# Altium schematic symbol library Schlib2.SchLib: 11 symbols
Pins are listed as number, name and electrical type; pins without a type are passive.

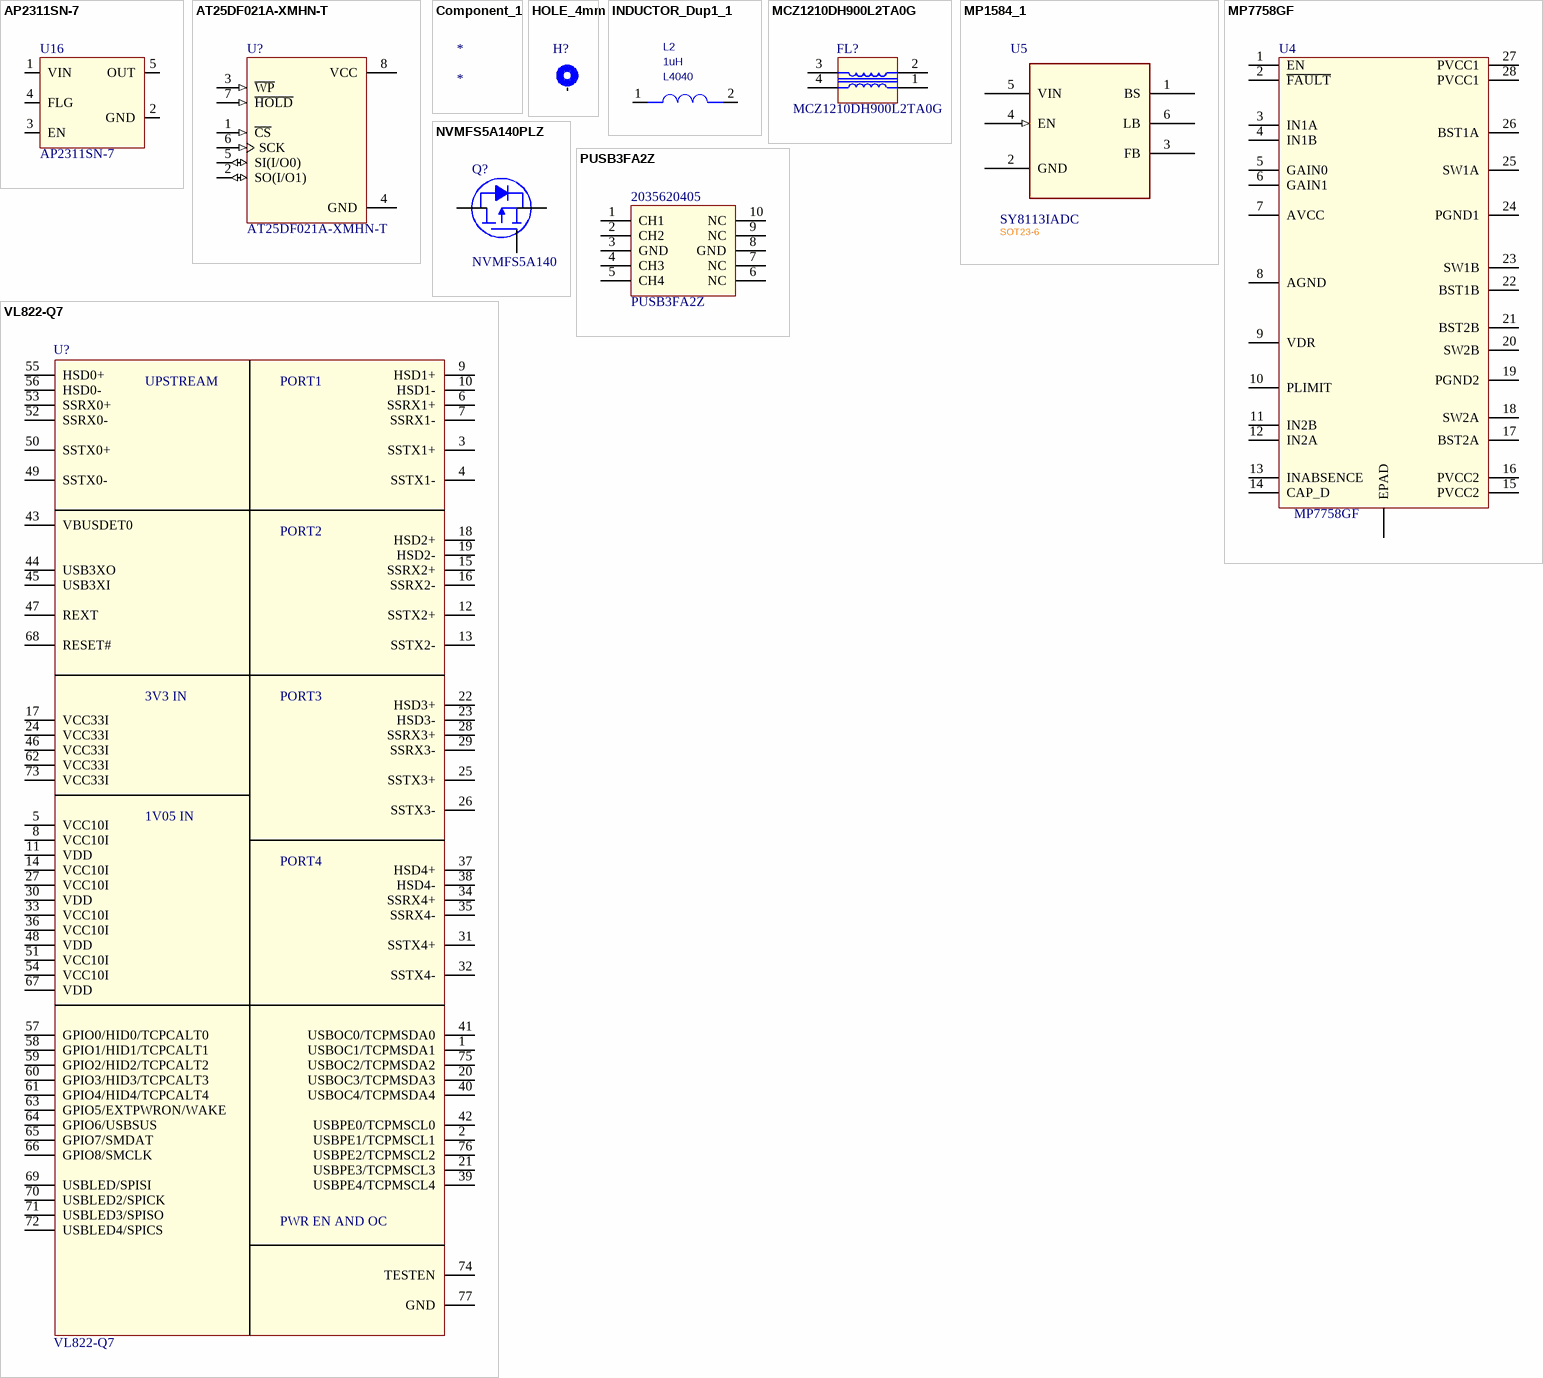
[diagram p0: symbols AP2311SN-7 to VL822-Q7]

## AP2311SN-7
designator U16
Power Switch ICs - Power Distribution 2.0A SGL CH 70mOhm 2.5A 2.7 to 5.5V
footprint AP2301SN-7 (Power Switch ICs - Power Distribution 2.0A SGL CH 70mOhm 2.5A 2.7 to 5.5V)
pins: 1 VIN, 2 GND, 3 EN, 4 FLG, 5 OUT

## AT25DF021A-XMHN-T
designator U?
IC FLASH 2MBIT SPI 104MHZ 8TSSOP
footprint AT25DF512C-XMHNGU-B (NOR Flash 512Kb, 1.65V, 85Mhz Serial Flash)
pins: 1 ~{CS} (in), 2 SO(I/O1) (io), 3 ~{WP} (in), 4 GND (power), 5 SI(I/O0) (io), 6 SCK (in), 7 ~{HOLD} (in), 8 VCC (power)

## Component_1
designator *

## HOLE_4mm
designator H?, comment HOLE_4.1mm  (value not drawn)
PART_NUMBER: PCB²âÊÔµã; Manufacturer: NA; Remarks: pcb; PCB Footprint: M2.0_3.6
footprint M2.0_3.6
pins: 1

## INDUCTOR_Dup1_1
designator L2, comment 1uH  PCB Footprint: L4040
PART_NUMBER: FDSD0420D-1R0M
footprint L4040
pins: 1, 2

## MCZ1210DH900L2TA0G
designator FL?
Common Mode Chokes / Filters 0504 90ohms 2 Lines HDMI, DVI, USB3.0; Manufacturer_Name: TDK; Manufacturer_Part_Number: MCZ1210DH500L2TA0G
footprint MCZ1210DH
pins: 1, 2, 3, 4

## MP1584_1
designator U5, comment SY8113IADC  PCB Footprint: SOT23-6
footprint SOT23-6
pins: 1 BS, 2 GND (power), 3 FB, 4 EN (in), 5 VIN (power), 6 LB

## MP7758GF
designator U4
Amplifier IC 2-Channel (Stereo) Class D 28-TSSOP-EP; Manufacturer: Monolithic Power Systems Inc.; Part Number: MP7758GF-Z
footprint MP7758GF (TSSOP-28)
pins: 1 EN, 2 ~{FAULT}, 3 IN1A, 4 IN1B, 5 GAIN0, 6 GAIN1, 7 AVCC, 8 AGND, 9 VDR, 10 PLIMIT, 11 IN2B, 12 IN2A, 13 INABSENCE, 14 CAP_D, 15 PVCC2, 16 PVCC2, 17 BST2A, 18 SW2A, 19 PGND2, 20 SW2B, 21 BST2B, 22 BST1B, 23 SW1B, 24 PGND1, 25 SW1A, 26 BST1A, 27 PVCC1, 28 PVCC1, EPAD

## NVMFS5A140PLZ
designator Q?, comment NVMFS5A140
Single P-Channel Power MOSFET, -40 V, -140 A; Part Number: BSZ067N06LS3GATMA1; Manufacturer: Infineon Technologies; Current - Continuous Drain (Id) @ 25°C: 14A (Ta), 20A (Tc); Drain to Source Voltage (Vdss): 60V; Drive Voltage (Max Rds On,  Min Rds On): 4.5V, 10V; FET Type: N-Channel; Gate Charge (Qg) (Max) @ Vgs: 67nC @ 10V; Input Capacitance (Ciss) (Max) @ Vds: 5100pF @ 30V; Power Dissipation (Max): 2.1W (Ta), 69W (Tc); Rds On (Max) @ Id, Vgs: 6.7mOhm @ 20A, 10V; Vgs (Max): ±20V; Vgs(th) (Max) @ Id: 2.2V @ 35µA
footprint NVMFS5A140PLZT1G
pins: 1 S, 2 S, 3 S, 4 G, 5 D, 6 D, 7 D, 8 D, 9 D

## PUSB3FA2Z
designator 2035620405
ESD Suppressors / TVS Diodes PUSB3FA2 XSON10; Manufacturer_Name: Nexperia
footprint PUSB3FR4Z
pins: 1 CH1, 2 CH2, 3 GND, 4 CH3, 5 CH4, 6 NC, 7 NC, 8 GND, 9 NC, 10 NC

## VL822-Q7
designator U?
USB3.2 GEN2 4 PORT USB HUB
footprint VL822-Q7 (USB 3.2 Gen 2x1  4-Port Hub Controller)
pins: 1 USBOC1/TCPMSDA1, 2 USBPE1/TCPMSCL1, 3 SSTX1+, 4 SSTX1-, 5 VCC10I, 6 SSRX1+, 7 SSRX1-, 8 VCC10I, 9 HSD1+, 10 HSD1-, 11 VDD, 12 SSTX2+, 13 SSTX2-, 14 VCC10I, 15 SSRX2+, 16 SSRX2-, 17 VCC33I, 18 HSD2+, 19 HSD2-, 20 USBOC3/TCPMSDA3, 21 USBPE3/TCPMSCL3, 22 HSD3+, 23 HSD3-, 24 VCC33I, 25 SSTX3+, 26 SSTX3-, 27 VCC10I, 28 SSRX3+, 29 SSRX3-, 30 VDD, 31 SSTX4+, 32 SSTX4-, 33 VCC10I, 34 SSRX4+, 35 SSRX4-, 36 VCC10I, 37 HSD4+, 38 HSD4-, 39 USBPE4/TCPMSCL4, 40 USBOC4/TCPMSDA4, 41 USBOC0/TCPMSDA0, 42 USBPE0/TCPMSCL0, 43 VBUSDET0, 44 USB3XO, 45 USB3XI, 46 VCC33I, 47 REXT, 48 VDD, 49 SSTX0-, 50 SSTX0+, 51 VCC10I, 52 SSRX0-, 53 SSRX0+, 54 VCC10I, 55 HSD0+, 56 HSD0-, 57 GPIO0/HID0/TCPCALT0, 58 GPIO1/HID1/TCPCALT1, 59 GPIO2/HID2/TCPCALT2, 60 GPIO3/HID3/TCPCALT3, 61 GPIO4/HID4/TCPCALT4, 62 VCC33I, 63 GPIO5/EXTPWRON/WAKE, 64 GPIO6/USBSUS, 65 GPIO7/SMDAT, 66 GPIO8/SMCLK, 67 VDD, 68 RESET#, 69 USBLED/SPISI, 70 USBLED2/SPICK, 71 USBLED3/SPISO, 72 USBLED4/SPICS, 73 VCC33I, 74 TESTEN, 75 USBOC2/TCPMSDA2, 76 USBPE2/TCPMSCL2, 77 GND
